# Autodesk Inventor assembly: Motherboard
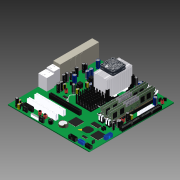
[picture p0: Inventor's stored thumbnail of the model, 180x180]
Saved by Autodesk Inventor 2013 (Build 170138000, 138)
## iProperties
Company: Autodesk Inc.
Created: 2005-12
Part Number: Motherboard
Document SubType Name: Assembly
Designer: Autodesk Inc.
Mass: 476.851 g
Surface Area: 5141.46 cm^2
Volume: 476.851 cm^3
Density: 1 g/cm^3
Title: Personal Computer
Author: Autodesk Inc.
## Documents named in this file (36)
- Z:\_DATEN\Personal Computer\Motherboard\Motherboard.iam
- Z:\_DATEN\Personal Computer\Motherboard\J9B1 Connector.ipt
- Z:\_DATEN\Personal Computer\Motherboard\J9C2 Connector.ipt
- Z:\_DATEN\Personal Computer\Motherboard\PCIE Connector.ipt
- Z:\_DATEN\Personal Computer\Motherboard\C9G5 connector.ipt
- Z:\_DATEN\Personal Computer\Motherboard\J9H2 Connector.ipt
- Z:\_DATEN\Personal Computer\Motherboard\PCI Slot.ipt
- Z:\_DATEN\Personal Computer\Motherboard\AGP slot.ipt
- Z:\_DATEN\Personal Computer\Motherboard\DDR Connector.ipt
- Z:\_DATEN\Personal Computer\Motherboard\RJ45 Module.ipt
- Z:\_DATEN\Personal Computer\Motherboard\USB Module.ipt
- Z:\_DATEN\Personal Computer\Motherboard\IO Interface Module.ipt
- Z:\_DATEN\Personal Computer\Motherboard\Capacitor 1000 UF.ipt
- Z:\_DATEN\Personal Computer\Motherboard\Capacitor 560 UF.ipt
- Z:\_DATEN\Personal Computer\Motherboard\Capacitor 1200 UF.ipt
- Z:\_DATEN\Personal Computer\Motherboard\Capacitor 640 UF.ipt
- Z:\_DATEN\Personal Computer\Motherboard\Capacitor 3000 UF.ipt
- Z:\_DATEN\Personal Computer\Motherboard\Choke.ipt
- Z:\_DATEN\Personal Computer\Motherboard\Battery.ipt
- Z:\_DATEN\Personal Computer\Motherboard\Bezel.ipt
- Z:\_DATEN\Personal Computer\Motherboard\Chip 15 x15.ipt
- Z:\_DATEN\Personal Computer\Motherboard\Capacitor 3500 UF.ipt
- Z:\_DATEN\Personal Computer\Motherboard\Chip block.ipt
- Z:\_DATEN\Personal Computer\Motherboard\Chip stand.ipt
- Z:\_DATEN\Personal Computer\Motherboard\Chip 13 x 6.ipt
- Z:\_DATEN\Personal Computer\Motherboard\Chip 22 x 11.ipt
- Z:\_DATEN\Personal Computer\Motherboard\Chip 24 x 23.ipt
- Z:\_DATEN\Personal Computer\Motherboard\RAM - DDR.ipt
- Z:\_DATEN\Personal Computer\Motherboard\Motherboard Heat Sink.ipt
- Z:\_DATEN\Personal Computer\Motherboard\IDE Male Connector.ipt
- Z:\_DATEN\Personal Computer\Motherboard\Processor Heat Sink Mounting.ipt
- Z:\_DATEN\Personal Computer\Motherboard\Processor Heat Sink.ipt
- Z:\_DATEN\Personal Computer\Motherboard\Motherboard PCB.ipt
- Z:\_DATEN\Personal Computer\Motherboard\Processor Fan\Cooling Fan, 40mm x 40mm x 10 mm, 12VDC.iam
- Z:\_DATEN\Personal Computer\Motherboard\Power Supply Header 2.ipt
- Z:\_DATEN\Personal Computer\Motherboard\Power Supply Header 1.ipt
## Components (111 placed, 35 different names)
1. PCI Slot:3
2. Motherboard PCB:1 — Mate:84, Mate:85, Mate:86, Mate:87, Mate:90, Mate:91, Mate:92
3. J9B1 Connector:1
4. J9B1 Connector:2
5. J9C2 Connector:1
6. PCIE Connector:1
7. C9G5 connector:1
8. J9H2 Connector:1
9. J9H2 Connector:2
10. C9G5 connector:2
11. IDE Male Connector:1
12. IDE Male Connector:2
13. Power Supply Header 1:1 — Mate:84, Mate:85, Mate:86
14. J9B1 Connector:3 — Mate:90, Mate:91, Mate:92
15. AGP slot:1
16. Processor Heat Sink Mounting:1
17. Processor Heat Sink:1 — Mate:83, Flush:18, Flush:19
18. RJ45 Module:1
19. USB Module:1
20. IO Interface Module:1
21. Capacitor 560 UF:1
22. Capacitor 1200 UF:1
23. Capacitor 560 UF:2
24. Capacitor 640 UF:1
25. Capacitor 640 UF:2
26. Capacitor 1000 UF:2
27. Capacitor 3000 UF:1
28. Capacitor 1200 UF:2
29. Capacitor 560 UF:8
30. Capacitor 560 UF:9
31. Capacitor 560 UF:10
32. Capacitor 560 UF:11
33. Capacitor 560 UF:12
34. Capacitor 3000 UF:2
35. Capacitor 3000 UF:3
36. Capacitor 3000 UF:4
37. Capacitor 3000 UF:5
38. Capacitor 560 UF:13
39. Capacitor 560 UF:14
40. Capacitor 1200 UF:3
41. Capacitor 1200 UF:4
42. Capacitor 1200 UF:5
43. Capacitor 640 UF:8
44. Capacitor 640 UF:9
45. Capacitor 640 UF:10
46. Capacitor 640 UF:11
47. Capacitor 640 UF:12
48. Capacitor 640 UF:13
49. Capacitor 3000 UF:6
50. Capacitor 560 UF:16
51. Capacitor 1200 UF:6
52. Capacitor 1200 UF:7
53. Capacitor 1200 UF:8
54. Capacitor 3000 UF:7
55. Choke:1
56. Choke:2
57. Choke:3
58. Battery:1
59. Bezel:1
60. Chip 15 x15:1
61. Capacitor 3500 UF:1
62. Capacitor 1000 UF:5
63. Capacitor 1000 UF:6
64. Capacitor 1200 UF:9
65. Capacitor 1200 UF:11
66. Capacitor 1200 UF:10
67. Capacitor 1200 UF:12
68. Capacitor 1000 UF:7
69. Capacitor 1000 UF:8
70. Capacitor 1000 UF:9
71. Chip block:1
72. Chip block:2
73. Chip block:3
74. Chip stand:1 — Flush:13
75. Chip stand:2 — Flush:9, Flush:10
76. Chip stand:3 — Flush:8, Flush:9
77. Chip stand:4 — Flush:7, Flush:8
78. Chip stand:5 — Flush:11, Flush:12, Flush:13
79. Chip stand:6 — Flush:16, Flush:17
80. Chip stand:7 — Flush:12
81. Chip stand:8 — Flush:6, Flush:7, Flush:10, Flush:11
82. Chip stand:9 — Flush:5, Flush:6
83. Chip stand:10 — Flush:5, Flush:17
84. Chip stand:11 — Flush:15, Flush:16
85. Chip stand:12 — Flush:14
86. Chip stand:13 — Flush:14, Flush:15
87. Chip 13 x 6:1
88. Chip 13 x 6:2
89. Chip 13 x 6:3
90. Chip 22 x 11:1
91. Chip 22 x 11:3
92. Chip 24 x 23:1
93. Chip 24 x 23:2
94. Choke:4
95. Choke:5
96. Choke:6
97. Choke:7
98. Capacitor 560 UF:17
99. Motherboard Heat Sink:1
100. Cooling Fan, 40mm x 40mm x 10 mm, 12VDC:1 [sub-assembly] — Mate:83, Flush:18, Flush:19
101. Power Supply Header 2:1 — Mate:87
102. PCI Slot:1
103. PCI Slot:2
104. DDR Connector:1 — Mate:80, Mate:81, Mate:82
105. DDR Connector:2
106. DDR Connector:3
107. DDR Connector:4
108. RAM - DDR:1 — Mate:80, Mate:81, Mate:82
109. RAM - DDR:2
110. RAM - DDR:3
111. RAM - DDR:4
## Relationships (26: Flush 15, Mate 11)
- Flush:5: Chip stand:9 ↔ Chip stand:10
- Flush:6: Chip stand:8 ↔ Chip stand:9
- Flush:7: Chip stand:4 ↔ Chip stand:8
- Flush:8: Chip stand:3 ↔ Chip stand:4
- Flush:9: Chip stand:2 ↔ Chip stand:3
- Flush:10: Chip stand:2 ↔ Chip stand:8
- Flush:11: Chip stand:5 ↔ Chip stand:8
- Flush:12: Chip stand:5 ↔ Chip stand:7
- Flush:13: Chip stand:1 ↔ Chip stand:5
- Flush:14: Chip stand:12 ↔ Chip stand:13
- Flush:15: Chip stand:11 ↔ Chip stand:13
- Flush:16: Chip stand:6 ↔ Chip stand:11
- Flush:17: Chip stand:6 ↔ Chip stand:10
- Mate:80: DDR Connector:1 ↔ RAM - DDR:1
- Mate:81: DDR Connector:1 ↔ RAM - DDR:1
- Mate:82: DDR Connector:1 ↔ RAM - DDR:1
- Mate:83: Processor Heat Sink:1 ↔ Cooling Fan, 40mm x 40mm x 10 mm, 12VDC:1
- Flush:18: Processor Heat Sink:1 ↔ Cooling Fan, 40mm x 40mm x 10 mm, 12VDC:1
- Flush:19: Processor Heat Sink:1 ↔ Cooling Fan, 40mm x 40mm x 10 mm, 12VDC:1
- Mate:84: Motherboard PCB:1 ↔ Power Supply Header 1:1
- Mate:85: Motherboard PCB:1 ↔ Power Supply Header 1:1
- Mate:86: Motherboard PCB:1 ↔ Power Supply Header 1:1
- Mate:87: Motherboard PCB:1 ↔ Power Supply Header 2:1
- Mate:90: Motherboard PCB:1 ↔ J9B1 Connector:3
- Mate:91: Motherboard PCB:1 ↔ J9B1 Connector:3
- Mate:92: Motherboard PCB:1 ↔ J9B1 Connector:3
